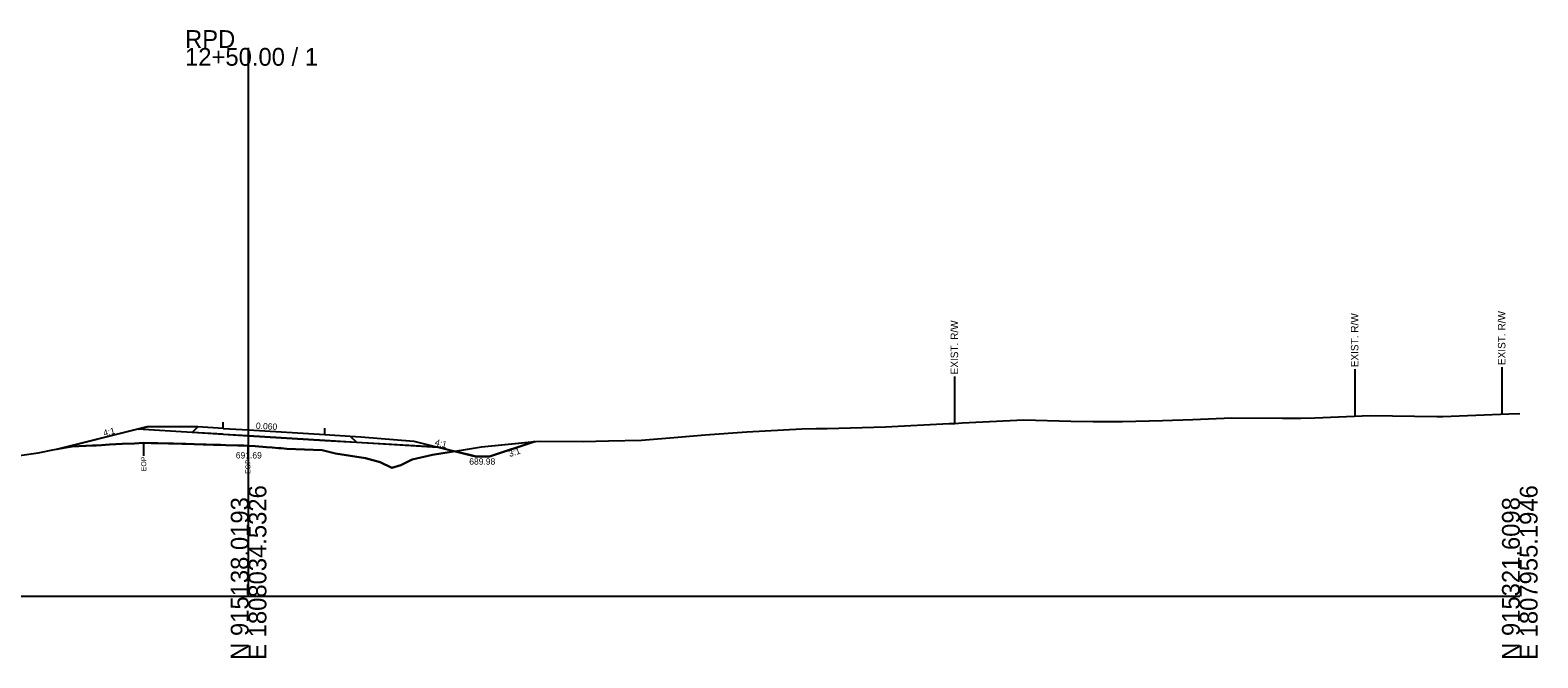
# Model space of a CAD drawing. Extents: x -26 to 403, y -10 to 8517.
# Drawn here: x 165.6 to 402.8, y 4990.3 to 5089.1 of the extents above; entities that cross this region are included whole.
import ezdxf

# ---------------------------------------------------------------- set-up
doc = ezdxf.new("R2010")
doc.units = 0
for name, color, linetype in [('Exist Cross Section Cell', 7, 'Continuous'), ('Exist XS Center Line Elevation Label', 7, 'Continuous'), ('Exist XS Ground Line', 7, 'Continuous'), ('Old_Level_10', 7, 'Continuous'), ('Prop XS Ditch Slope Text', 7, 'Continuous'), ('Prop XS Ditch Standard Text', 7, 'Continuous'), ('Prop XS Earthwork Shape', 7, 'Continuous'), ('Prop XS EOT Tick Mark', 7, 'Continuous'), ('Prop XS Finish Grade', 7, 'Continuous'), ('Prop XS Finish Grade Earthwork', 7, 'Continuous'), ('Prop XS Finish Grade Paved Shoulder', 7, 'Continuous'), ('Prop XS Finish Grade Pavement', 7, 'Continuous'), ('Prop XS Hydro Fill Slope Data', 7, 'Continuous'), ('Prop XS Pvmt Edge Slope', 7, 'Continuous'), ('Prop XS SE Text', 7, 'Continuous'), ('Prop XS Side Slope Text', 7, 'Continuous'), ('Prop XS Subgrade Earthwork', 7, 'Continuous')]:
    doc.layers.add(name, color=color, linetype=linetype)

msp = doc.modelspace()

# ---------------------------------------------------------------- linework, layer by layer
at = {"layer": 'Exist Cross Section Cell'}
for p, q in [((200, 5000), (200, 5086.31)), ((0, 5000), (200, 5000)), ((200, 5000), (400, 5000))]:
    msp.add_line(p, q, dxfattribs=at)
at = {"layer": 'Exist XS Ground Line'}
msp.add_lwpolyline([(161.01, 5021.73), (166.92, 5022.6), (169.47, 5023.09), (172.22, 5023.58), (175.43, 5023.74), (176.01, 5023.76), (176.84, 5023.8), (178.1, 5023.87), (180.1, 5023.98), (182.07, 5024.03), (183.49, 5024.14), (184.68, 5024.12), (185.74, 5024.09), (187.4, 5024.06), (188.2, 5024.03), (189.54, 5024), (190.12, 5023.98), (191.44, 5023.95), (192.85, 5023.91), (193.33, 5023.89), (194.46, 5023.86), (195.24, 5023.84), (195.57, 5023.83), (196.42, 5023.8), (198.3, 5023.74), (199.26, 5023.72), (199.9, 5023.7), (201.02, 5023.61), (202.84, 5023.49), (203.72, 5023.4), (204.68, 5023.31), (205.15, 5023.3), (206.03, 5023.23), (211.58, 5023), (213.69, 5022.48), (218.41, 5021.73), (220.69, 5021.12), (222.53, 5020.22), (223.94, 5020.66), (225.72, 5021.53), (228.95, 5022.25), (231.56, 5022.7), (235.38, 5023.31), (236.63, 5023.5), (245.73, 5024.43), (252.66, 5024.36), (256.63, 5024.49), (261.84, 5024.57), (267.52, 5025.05), (271.84, 5025.4), (278.41, 5025.91), (287.05, 5026.36), (289.31, 5026.41), (291.03, 5026.42), (300.2, 5026.67), (310.21, 5027.19), (311.1, 5027.22), (312.26, 5027.31), (321.99, 5027.79), (329.39, 5027.59), (332.88, 5027.49), (337.47, 5027.53), (343.78, 5027.68), (348.58, 5027.84), (354.67, 5028.11), (362.68, 5028.05), (365.56, 5028.03), (367.76, 5028.11), (376.46, 5028.44), (386.95, 5028.29), (387.35, 5028.29), (387.89, 5028.29), (398.25, 5028.73), (400, 5028.77)], dxfattribs=at)
at = {"layer": 'Old_Level_10'}
for p, q in [((397.15, 5036.09), (397.15, 5028.69)), ((311.04, 5034.62), (311.04, 5027.22)), ((374.02, 5035.75), (374.02, 5028.35)), ((183.49, 5024.14), (183.49, 5022.09)), ((199.9, 5023.7), (199.9, 5021.65))]:
    msp.add_line(p, q, dxfattribs=at)
at = {"layer": 'Prop XS Earthwork Shape'}
for points in [[(216.98, 5024.27), (229.78, 5023.51), (232.44, 5022.84), (231.56, 5022.7), (228.95, 5022.25), (225.72, 5021.53), (223.94, 5020.66), (222.53, 5020.22), (220.69, 5021.12), (218.41, 5021.73), (213.69, 5022.48), (211.58, 5023), (206.03, 5023.23), (205.15, 5023.3), (204.68, 5023.31), (203.72, 5023.4), (202.84, 5023.49), (201.02, 5023.61), (199.9, 5023.7), (199.26, 5023.72), (198.3, 5023.74), (196.42, 5023.8), (195.57, 5023.83), (195.24, 5023.84), (194.46, 5023.86), (193.33, 5023.89), (192.85, 5023.91), (191.44, 5023.95), (190.12, 5023.98), (189.54, 5024), (188.2, 5024.03), (187.4, 5024.06), (185.74, 5024.09), (184.68, 5024.12), (183.49, 5024.14), (182.07, 5024.03), (180.1, 5023.98), (178.1, 5023.87), (176.84, 5023.8), (176.01, 5023.76), (175.43, 5023.74), (172.22, 5023.58), (169.92, 5023.17), (182.59, 5026.34), (191.13, 5025.82), (195.98, 5025.53), (199.98, 5025.29), (211.98, 5024.57)], [(232.44, 5022.84), (235.38, 5023.31), (236.63, 5023.5), (245.03, 5024.36), (237.88, 5021.98), (235.88, 5021.98)]]:
    msp.add_lwpolyline(points, close=True, dxfattribs=at)
at = {"layer": 'Prop XS EOT Tick Mark'}
for p, q in [((196, 5026.42), (196, 5027.42)), ((212, 5025.46), (212, 5026.46))]:
    msp.add_line(p, q, dxfattribs=at)
at = {"layer": 'Prop XS Finish Grade'}
for p, q in [((182.59, 5026.3), (184, 5026.66)), ((190.43, 5026.66), (184, 5026.66)), ((192, 5026.66), (190.43, 5026.66)), ((216, 5025.22), (217.64, 5025.09)), ((217.64, 5025.09), (226, 5024.42)), ((226, 5024.42), (229.78, 5023.47))]:
    msp.add_line(p, q, dxfattribs=at)
at = {"layer": 'Prop XS Finish Grade Earthwork'}
for p, q in [((182.59, 5026.3), (169.92, 5023.14)), ((237.88, 5021.98), (245.03, 5024.36)), ((229.78, 5023.47), (235.88, 5021.95)), ((235.88, 5021.98), (237.88, 5021.98))]:
    msp.add_line(p, q, dxfattribs=at)
at = {"layer": 'Prop XS Finish Grade Paved Shoulder'}
for p, q in [((196, 5026.42), (192, 5026.66)), ((212, 5025.46), (216, 5025.22))]:
    msp.add_line(p, q, dxfattribs=at)
at = {"layer": 'Prop XS Finish Grade Pavement'}
for p, q in [((196, 5026.42), (200, 5026.18)), ((200, 5026.18), (212, 5025.46))]:
    msp.add_line(p, q, dxfattribs=at)
at = {"layer": 'Prop XS Hydro Fill Slope Data'}
msp.add_line((184, 5026.66), (169.92, 5023.14), dxfattribs=at)
at = {"layer": 'Prop XS Pvmt Edge Slope'}
for p, q in [((192, 5026.66), (191.13, 5025.79)), ((216, 5025.22), (216.98, 5024.24))]:
    msp.add_line(p, q, dxfattribs=at)
at = {"layer": 'Prop XS Subgrade Earthwork'}
for p, q in [((191.13, 5025.79), (182.59, 5026.3)), ((195.98, 5025.5), (191.13, 5025.79)), ((195.98, 5025.5), (199.98, 5025.26)), ((199.98, 5025.26), (211.98, 5024.54)), ((211.98, 5024.54), (216.98, 5024.24)), ((216.98, 5024.24), (229.78, 5023.47))]:
    msp.add_line(p, q, dxfattribs=at)

# ---------------------------------------------------------------- texts
at = {"layer": 'Exist Cross Section Cell'}
for s, p in [('RPD', (190, 5086.31)), ('12+50.00 / 1', (190, 5083.51))]:
    msp.add_text(s, height=2.8, dxfattribs=at).set_placement(p)
for s, p in [('E 1808034.5326', (202.8, 4990)), ('E 1807955.1946', (402.8, 4990)), ('N 915138.0193', (200, 4990)), ('N 915321.6098', (400, 4990))]:
    msp.add_text(s, height=2.8, rotation=90, dxfattribs=at).set_placement(p)
at = {"layer": 'Exist XS Center Line Elevation Label'}
msp.add_text('691.69', height=1, dxfattribs=at).set_placement((197.99, 5021.69))
at = {"layer": 'Old_Level_10'}
for s, height, rotation, p in [('EXIST. R/W', 1.181, 90, (311.63, 5034.92)), ('EXIST. R/W', 1.181, 90, (374.61, 5036.05)), ('EXIST. R/W', 1.181, 90, (397.74, 5036.39)), ('EOP', 0.787, 90, (183.89, 5019.69)), ('3:1', 1, 18.4349, (241.09, 5021.91)), ('EOP', 0.787, 90, (200.29, 5019.25))]:
    msp.add_text(s, height=height, rotation=rotation, dxfattribs=at).set_placement(p)
at = {"layer": 'Prop XS Ditch Slope Text'}
msp.add_text('4:1', height=1, rotation=345.9638, dxfattribs=at).set_placement((229.24, 5023.8))
at = {"layer": 'Prop XS Ditch Standard Text'}
msp.add_text('689.98', height=1, dxfattribs=at).set_placement((234.72, 5020.72))
at = {"layer": 'Prop XS SE Text'}
msp.add_text('0.060', height=1, rotation=356.5664, dxfattribs=at).set_placement((201.13, 5026.37))
at = {"layer": 'Prop XS Side Slope Text'}
msp.add_text('4:1', height=1, rotation=14.0362, dxfattribs=at).set_placement((177.27, 5025.17))

doc.saveas('drawing.dxf')
